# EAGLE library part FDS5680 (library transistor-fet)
60V N-Channel PowerTrench TM MOSFET FAIRCHILD FDS5680.pdf
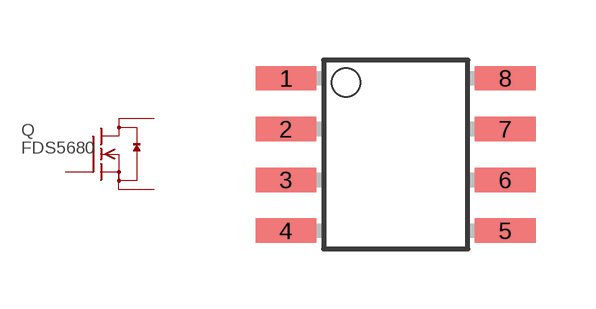
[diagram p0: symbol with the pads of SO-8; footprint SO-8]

Designator prefix Q

## FDS5680  [SO-8]
1  S1  pas
2  S2  pas
3  S3  pas
4  G  pas
5  D1  pas
6  D2  pas
7  D3  pas
8  D4  pas

## Footprint SO-8 (pad centres in mm)
SO 8 small outline
smd 1.524 x 0.61: 1 -2.743,1.905; 2 -2.743,0.635; 3 -2.743,-0.635; 4 -2.743,-1.905; 5 2.743,-1.905; 6 2.743,-0.635; 7 2.743,0.635; 8 2.743,1.905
